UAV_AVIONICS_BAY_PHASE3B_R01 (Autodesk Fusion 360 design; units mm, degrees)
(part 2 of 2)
extrude "Extrude1" new body sketch "SK_Fastener_Head" along normal blind 0.6
sketch "SK_Fastener_Shank" plane through (0, 0, 0) normal (0, 0, 1) x axis (1, 0, 0)
  circle C1 centre (0, 0) radius 1.25
extrude "Extrude2" add sketch "SK_Fastener_Shank" against normal blind 2
copy_paste "CopyPaste111"
copy_paste "CopyPaste112"
copy_paste "CopyPaste113"
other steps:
create_component "CreateComponent1"
create_component "CreateComponent2"
create_component "CreateComponent3"
create_component "CreateComponent4"
create_component "CreateComponent5"
create_component "CreateComponent6"
create_component "CreateComponent7"
create_component "CreateComponent8"
create_component "CreateComponent1"
create_component "CreateComponent2"
create_component "CreateComponent3"
create_component "CreateComponent4"
create_component "CreateComponent5"
create_component "CreateComponent1"
create_component "CreateComponent2"
create_component "CreateComponent3"
create_component "CreateComponent1"
create_component "CreateComponent2"
create_component "CreateComponent3" sketch "SK_PDB-03-303_Deck_Standoff_M2_5x6_Body"
create_component "CreateComponent4" sketch "SK_PDB-03-304_PCB_Standoff_M2x4_Body"
create_component "CreateComponent1"
create_component "CreateComponent2"
create_component "CreateComponent3"
create_component "CreateComponent4"
create_component "CreateComponent5"
create_component "CreateComponent6"
create_component "CreateComponent1"
create_component "CreateComponent2"
create_component "CreateComponent3"
create_component "CreateComponent4"
create_component "CreateComponent1"
create_component "CreateComponent2"
create_component "CreateComponent3"
create_component "CreateComponent4"
create_component "CreateComponent1"
create_component "CreateComponent2"
create_component "CreateComponent3"
create_component "CreateComponent4"
create_component "CreateComponent1"
create_component "CreateComponent2" sketch "SK_Hardware_Ring"
create_component "CreateComponent3" sketch "SK_Hardware_Ring"
create_component "CreateComponent4"
create_component "CreateComponent5" sketch "SK_Hardware_Ring"
create_component "CreateComponent6"
create_component "CreateComponent7"
create_component "CreateComponent8"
